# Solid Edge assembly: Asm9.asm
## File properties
Author: Blackblade
Template: Normal.asm
Last saved by: Blackblade
Revision: 9
Application: Solid Edge
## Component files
antenn2.par
tool.par
armatuur.psm
rool.par
trepp.par
gaasi_kang.par
luuk.par
kere_webs.par
parda_serv.par
tagumine_kate.psm
parem_punkri_aar.psm
vasak_punkri_aar.psm
eesmine_kate.psm
punker_kant.par
aken_.par
soudekruvi.par
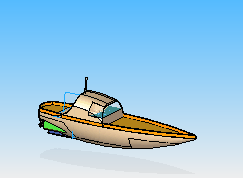
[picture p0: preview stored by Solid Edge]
